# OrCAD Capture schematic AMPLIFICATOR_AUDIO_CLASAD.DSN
size B
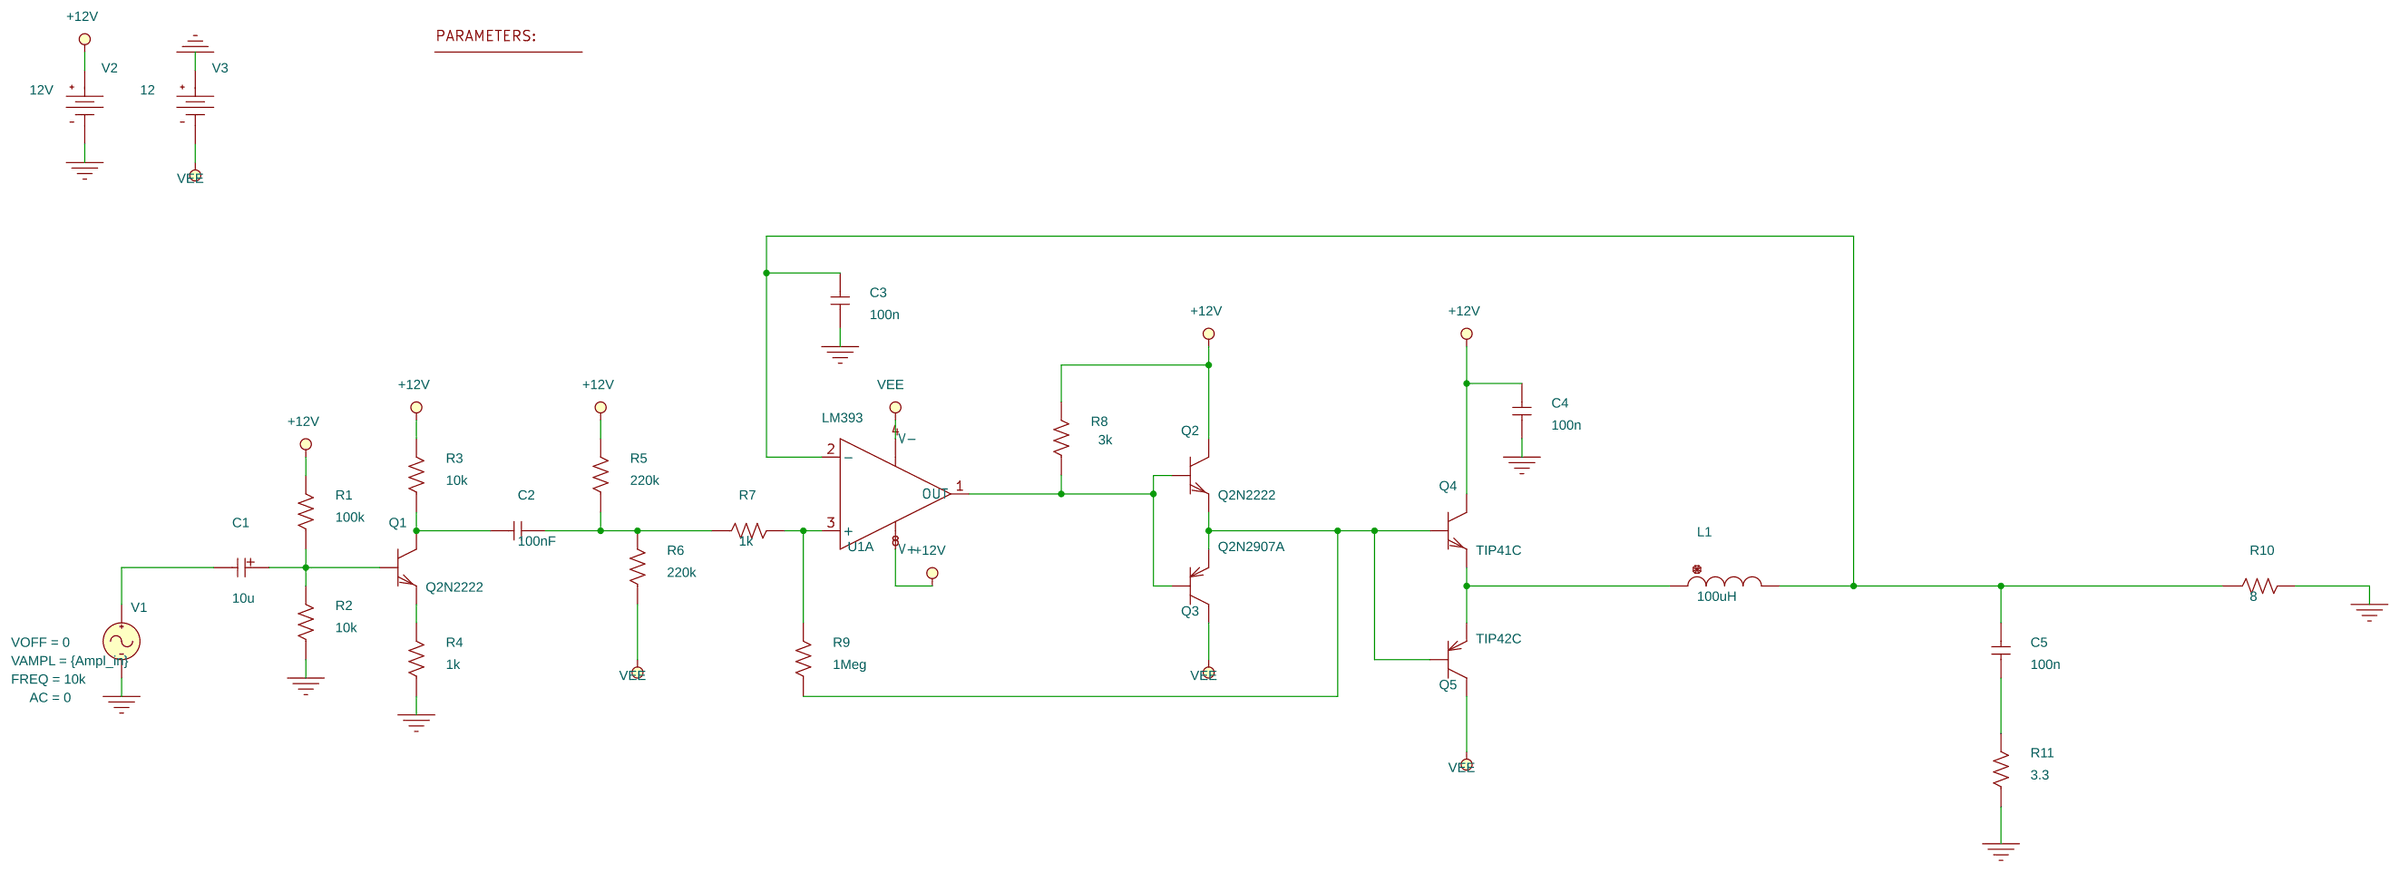
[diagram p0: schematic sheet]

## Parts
1  PARAM
C1  10u  [CPAX575x150031]
C2  100nF  [cap196]
C3  100n  [cap196]
C4  100n  [cap196]
C5  100n  [cap196]
L1  100uH  [DISC350x175LS200x100034]
Q1  Q2N2222  [TO18]
Q2  Q2N2222  [TO18]
Q3  Q2N2907A  [to206aa]
Q4  TIP41C  [to220ab]
Q5  TIP42C  [to220ab]
R1  100k  [AXRC05]
R2  10k  [AXRC05]
R3  10k  [AXRC05]
R4  1k  [AXRC05]
R5  220k  [AXRC05]
R6  220k  [AXRC05]
R7  1k  [AXRC05]
R8  3k  [AXRC05]
R9  1Meg  [AXRC05]
R10  8  [AXRC05]
R11  3.3  [AXRC05]
U1  LM393  [DIP1008W300L450]  (section A)
V1  VSIN
V2  VDC
V3  VDC

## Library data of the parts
1 = PARAM: Ampl_in: 100m
C1 = C_elect
C2-C5 = C
L1 = L
Q1 Q2 = Q2N2222
Q3 = Q2N2907A
Q4 = TIP41C
Q5 = TIP42C
R1-R11 = R
U1 = LM393
V1 = VSIN: AC: 0; AppProp: Sine$Voltage$0$-1; DC: 0; FREQ: 10k; TD: 500n; VAMPL: {Ampl_in}; VOFF: 0
V2 = VDC: DC: 12V
V3 = VDC: DC: 12

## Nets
+12V: C4.2 Q2.3(c) Q4.2(c) R1.2 R3.2 R5.2 R8.2 U1.8(V+) V2.0(+)
VEE: Q3.3(c) Q5.2(c) R6.1 U1.4(V-) V3.1(-)
0: C3.1 C4.1 R2.1 R4.1 R10.2 R11.1 V1.2(-) V2.1(-) V3.0(+)
N00154: C1.N(-) V1.1(+)
N00247: C1.P(+) Q1.2(b) R1.1 R2.2
N00431: Q1.1(e) R4.2
N00444: C2.1 Q1.3(c) R3.1
N00746: C2.2 R5.1 R6.2 R7.1
N00948: R7.2 R9.2 U1.3(+)
N01075: Q2.2(b) Q3.2(b) R8.1 U1.1(OUT)
N01115: C3.2 C5.2 L1.2 R10.1 U1.2(-)
N01288: Q2.1(e) Q3.1(e) Q4.1(b) Q5.1(b) R9.1
N01470: L1.1 Q4.3(e) Q5.3(e)
N01973: C5.1 R11.2
